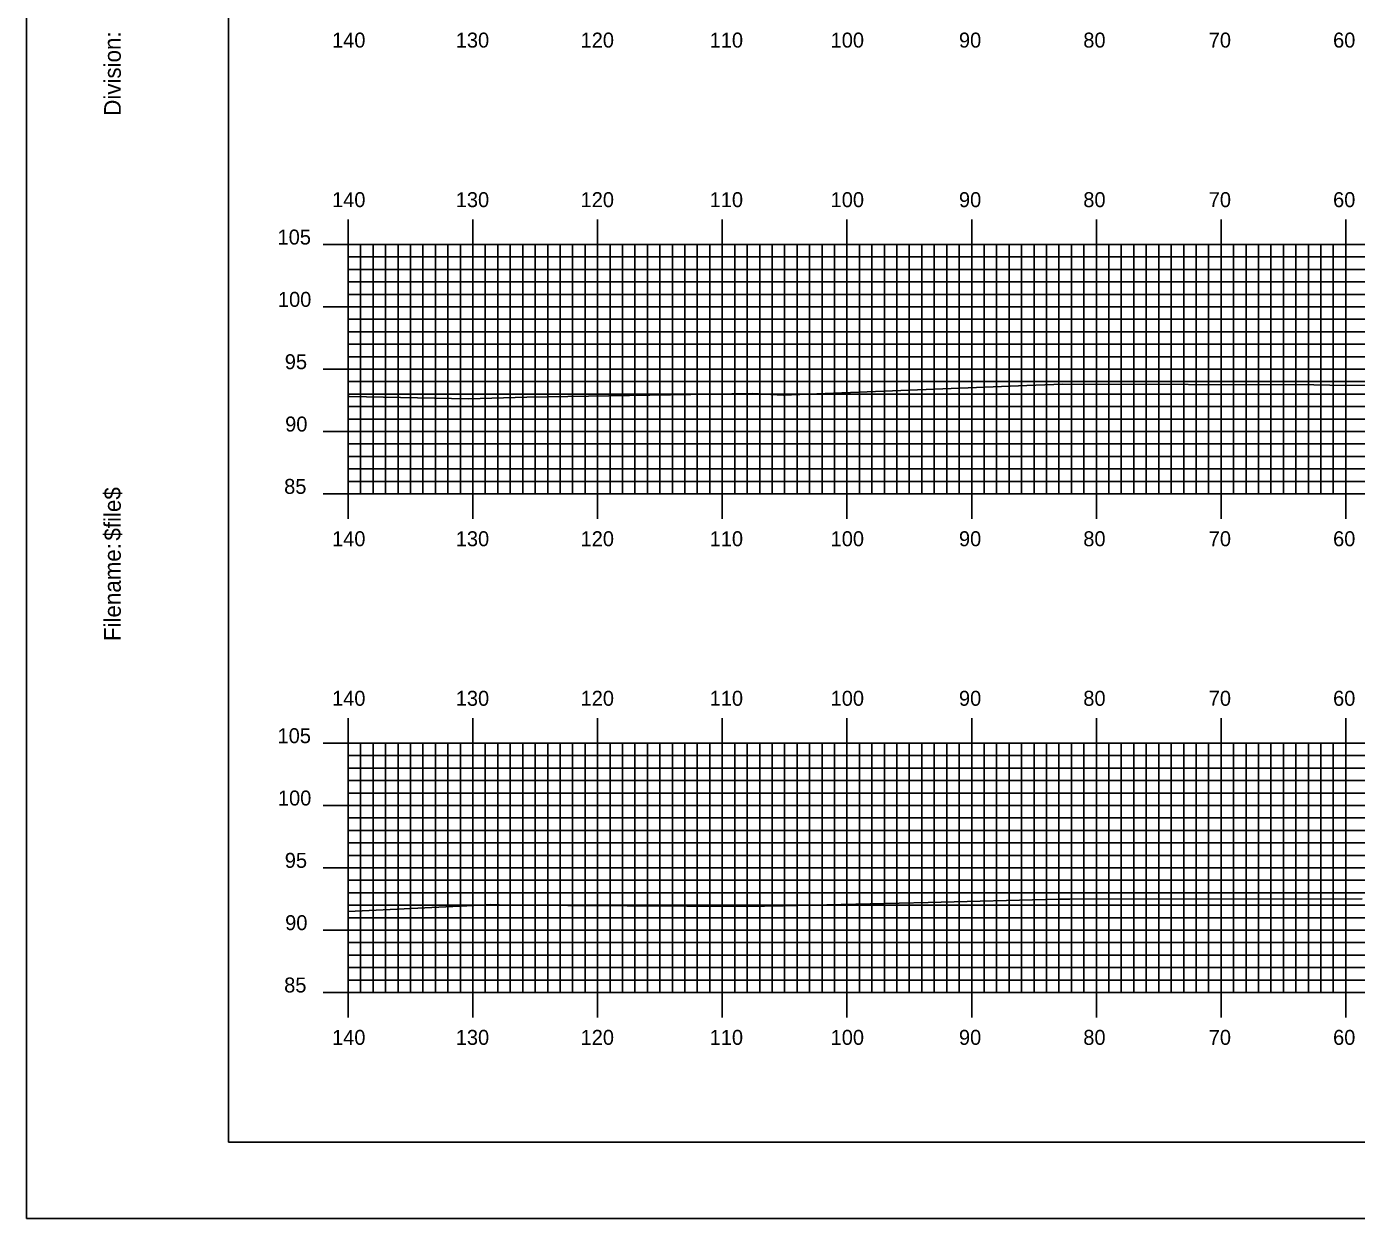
# Model space of a CAD drawing. Extents: x 1778319 to 1778662, y 442591 to 442811.
# Drawn here: x 1778318.5 to 1778425.2, y 442590.5 to 442686.2 of the extents above; entities that cross this region are included whole.
import ezdxf

# ---------------------------------------------------------------- set-up
doc = ezdxf.new("R2010")
doc.units = 0
for name, color, linetype in [('BORDER', 7, 'Continuous'), ('H_V ANNOTATION', 7, 'Continuous'), ('MAJOR', 7, 'Continuous'), ('MINOR', 7, 'Continuous'), ('PLOT BOUNDARY', 7, 'Continuous'), ('S_Roadway_Centerline', 7, 'Continuous')]:
    doc.layers.add(name, color=color, linetype=linetype)

msp = doc.modelspace()

# ---------------------------------------------------------------- linework, layer by layer
at = {"layer": 'BORDER'}
msp.add_lwpolyline([(1778334.7, 442596.67), (1778654.7, 442596.67), (1778654.7, 442806.67), (1778334.7, 442806.67)], close=True, dxfattribs=at)
at = {"layer": 'MAJOR'}
for p, q in [((1778344.3, 442670.67), (1778344.3, 442668.67)), ((1778354.3, 442670.67), (1778354.3, 442668.67)), ((1778364.3, 442670.67), (1778364.3, 442668.67)), ((1778374.3, 442670.67), (1778374.3, 442668.67)), ((1778384.3, 442670.67), (1778384.3, 442668.67)), ((1778394.3, 442670.67), (1778394.3, 442668.67)), ((1778404.3, 442670.67), (1778404.3, 442668.67)), ((1778414.3, 442670.67), (1778414.3, 442668.67)), ((1778424.3, 442670.67), (1778424.3, 442668.67)), ((1778342.3, 442668.67), (1778344.3, 442668.67)), ((1778344.3, 442668.67), (1778624.3, 442668.67)), ((1778344.3, 442648.67), (1778344.3, 442668.67)), ((1778344.3, 442648.67), (1778344.3, 442668.67)), ((1778344.3, 442668.67), (1778624.3, 442668.67)), ((1778354.3, 442648.67), (1778354.3, 442668.67)), ((1778364.3, 442648.67), (1778364.3, 442668.67)), ((1778374.3, 442648.67), (1778374.3, 442668.67)), ((1778384.3, 442648.67), (1778384.3, 442668.67)), ((1778394.3, 442648.67), (1778394.3, 442668.67)), ((1778404.3, 442648.67), (1778404.3, 442668.67)), ((1778414.3, 442648.67), (1778414.3, 442668.67)), ((1778424.3, 442648.67), (1778424.3, 442668.67)), ((1778342.3, 442663.67), (1778344.3, 442663.67)), ((1778344.3, 442663.67), (1778624.3, 442663.67)), ((1778342.3, 442658.67), (1778344.3, 442658.67)), ((1778344.3, 442658.67), (1778624.3, 442658.67)), ((1778342.3, 442653.67), (1778344.3, 442653.67)), ((1778344.3, 442653.67), (1778624.3, 442653.67)), ((1778342.3, 442648.67), (1778344.3, 442648.67)), ((1778344.3, 442648.67), (1778624.3, 442648.67)), ((1778344.3, 442648.67), (1778624.3, 442648.67)), ((1778344.3, 442646.66), (1778344.3, 442648.67)), ((1778354.3, 442646.66), (1778354.3, 442648.67)), ((1778364.3, 442646.66), (1778364.3, 442648.67)), ((1778374.3, 442646.66), (1778374.3, 442648.67)), ((1778384.3, 442646.66), (1778384.3, 442648.67)), ((1778394.3, 442646.66), (1778394.3, 442648.67)), ((1778404.3, 442646.66), (1778404.3, 442648.67)), ((1778414.3, 442646.66), (1778414.3, 442648.67)), ((1778424.3, 442646.66), (1778424.3, 442648.67)), ((1778344.3, 442630.67), (1778344.3, 442628.67)), ((1778354.3, 442630.67), (1778354.3, 442628.67)), ((1778364.3, 442630.67), (1778364.3, 442628.67)), ((1778374.3, 442630.67), (1778374.3, 442628.67)), ((1778384.3, 442630.67), (1778384.3, 442628.67)), ((1778394.3, 442630.67), (1778394.3, 442628.67)), ((1778404.3, 442630.67), (1778404.3, 442628.67)), ((1778414.3, 442630.67), (1778414.3, 442628.67)), ((1778424.3, 442630.67), (1778424.3, 442628.67)), ((1778342.3, 442628.67), (1778344.3, 442628.67)), ((1778344.3, 442628.67), (1778624.3, 442628.67)), ((1778344.3, 442608.67), (1778344.3, 442628.67)), ((1778344.3, 442608.67), (1778344.3, 442628.67)), ((1778344.3, 442628.67), (1778624.3, 442628.67)), ((1778354.3, 442608.67), (1778354.3, 442628.67)), ((1778364.3, 442608.67), (1778364.3, 442628.67)), ((1778374.3, 442608.67), (1778374.3, 442628.67)), ((1778384.3, 442608.67), (1778384.3, 442628.67)), ((1778394.3, 442608.67), (1778394.3, 442628.67)), ((1778404.3, 442608.67), (1778404.3, 442628.67)), ((1778414.3, 442608.67), (1778414.3, 442628.67)), ((1778424.3, 442608.67), (1778424.3, 442628.67)), ((1778342.3, 442623.67), (1778344.3, 442623.67)), ((1778344.3, 442623.67), (1778624.3, 442623.67)), ((1778342.3, 442618.67), (1778344.3, 442618.67)), ((1778344.3, 442618.67), (1778624.3, 442618.67)), ((1778342.3, 442613.67), (1778344.3, 442613.67)), ((1778344.3, 442613.67), (1778624.3, 442613.67)), ((1778342.3, 442608.67), (1778344.3, 442608.67)), ((1778344.3, 442608.67), (1778624.3, 442608.67)), ((1778344.3, 442608.67), (1778624.3, 442608.67)), ((1778344.3, 442606.66), (1778344.3, 442608.67)), ((1778354.3, 442606.66), (1778354.3, 442608.67)), ((1778364.3, 442606.66), (1778364.3, 442608.67)), ((1778374.3, 442606.66), (1778374.3, 442608.67)), ((1778384.3, 442606.66), (1778384.3, 442608.67)), ((1778394.3, 442606.66), (1778394.3, 442608.67)), ((1778404.3, 442606.66), (1778404.3, 442608.67)), ((1778414.3, 442606.66), (1778414.3, 442608.67)), ((1778424.3, 442606.66), (1778424.3, 442608.67))]:
    msp.add_line(p, q, dxfattribs=at)
at = {"layer": 'MINOR'}
for p, q in [((1778345.3, 442648.67), (1778345.3, 442668.67)), ((1778346.3, 442648.67), (1778346.3, 442668.67)), ((1778347.3, 442648.67), (1778347.3, 442668.67)), ((1778348.3, 442648.67), (1778348.3, 442668.67)), ((1778349.3, 442648.67), (1778349.3, 442668.67)), ((1778350.3, 442648.67), (1778350.3, 442668.67)), ((1778351.3, 442648.67), (1778351.3, 442668.67)), ((1778352.3, 442648.67), (1778352.3, 442668.67)), ((1778353.3, 442648.67), (1778353.3, 442668.67)), ((1778355.3, 442648.67), (1778355.3, 442668.67)), ((1778356.3, 442648.67), (1778356.3, 442668.67)), ((1778357.3, 442648.67), (1778357.3, 442668.67)), ((1778358.3, 442648.67), (1778358.3, 442668.67)), ((1778359.3, 442648.67), (1778359.3, 442668.67)), ((1778360.3, 442648.67), (1778360.3, 442668.67)), ((1778361.3, 442648.67), (1778361.3, 442668.67)), ((1778362.3, 442648.67), (1778362.3, 442668.67)), ((1778363.3, 442648.67), (1778363.3, 442668.67)), ((1778365.3, 442648.67), (1778365.3, 442668.67)), ((1778366.3, 442648.67), (1778366.3, 442668.67)), ((1778367.3, 442648.67), (1778367.3, 442668.67)), ((1778368.3, 442648.67), (1778368.3, 442668.67)), ((1778369.3, 442648.67), (1778369.3, 442668.67)), ((1778370.3, 442648.67), (1778370.3, 442668.67)), ((1778371.3, 442648.67), (1778371.3, 442668.67)), ((1778372.3, 442648.67), (1778372.3, 442668.67)), ((1778373.3, 442648.67), (1778373.3, 442668.67)), ((1778375.3, 442648.67), (1778375.3, 442668.67)), ((1778376.3, 442648.67), (1778376.3, 442668.67)), ((1778377.3, 442648.67), (1778377.3, 442668.67)), ((1778378.3, 442648.67), (1778378.3, 442668.67)), ((1778379.3, 442648.67), (1778379.3, 442668.67)), ((1778380.3, 442648.67), (1778380.3, 442668.67)), ((1778381.3, 442648.67), (1778381.3, 442668.67)), ((1778382.3, 442648.67), (1778382.3, 442668.67)), ((1778383.3, 442648.67), (1778383.3, 442668.67)), ((1778385.3, 442648.67), (1778385.3, 442668.67)), ((1778386.3, 442648.67), (1778386.3, 442668.67)), ((1778387.3, 442648.67), (1778387.3, 442668.67)), ((1778388.3, 442648.67), (1778388.3, 442668.67)), ((1778389.3, 442648.67), (1778389.3, 442668.67)), ((1778390.3, 442648.67), (1778390.3, 442668.67)), ((1778391.3, 442648.67), (1778391.3, 442668.67)), ((1778392.3, 442648.67), (1778392.3, 442668.67)), ((1778393.3, 442648.67), (1778393.3, 442668.67)), ((1778395.3, 442648.67), (1778395.3, 442668.67)), ((1778396.3, 442648.67), (1778396.3, 442668.67)), ((1778397.3, 442648.67), (1778397.3, 442668.67)), ((1778398.3, 442648.67), (1778398.3, 442668.67)), ((1778399.3, 442648.67), (1778399.3, 442668.67)), ((1778400.3, 442648.67), (1778400.3, 442668.67)), ((1778401.3, 442648.67), (1778401.3, 442668.67)), ((1778402.3, 442648.67), (1778402.3, 442668.67)), ((1778403.3, 442648.67), (1778403.3, 442668.67)), ((1778405.3, 442648.67), (1778405.3, 442668.67)), ((1778406.3, 442648.67), (1778406.3, 442668.67)), ((1778407.3, 442648.67), (1778407.3, 442668.67)), ((1778408.3, 442648.67), (1778408.3, 442668.67)), ((1778409.3, 442648.67), (1778409.3, 442668.67)), ((1778410.3, 442648.67), (1778410.3, 442668.67)), ((1778411.3, 442648.67), (1778411.3, 442668.67)), ((1778412.3, 442648.67), (1778412.3, 442668.67)), ((1778413.3, 442648.67), (1778413.3, 442668.67)), ((1778415.3, 442648.67), (1778415.3, 442668.67)), ((1778416.3, 442648.67), (1778416.3, 442668.67)), ((1778417.3, 442648.67), (1778417.3, 442668.67)), ((1778418.3, 442648.67), (1778418.3, 442668.67)), ((1778419.3, 442648.67), (1778419.3, 442668.67)), ((1778420.3, 442648.67), (1778420.3, 442668.67)), ((1778421.3, 442648.67), (1778421.3, 442668.67)), ((1778422.3, 442648.67), (1778422.3, 442668.67)), ((1778423.3, 442648.67), (1778423.3, 442668.67)), ((1778344.3, 442667.67), (1778624.3, 442667.67)), ((1778344.3, 442667.67), (1778346.31, 442667.67)), ((1778344.3, 442666.67), (1778624.3, 442666.67)), ((1778344.3, 442666.67), (1778346.31, 442666.67)), ((1778344.3, 442665.67), (1778624.3, 442665.67)), ((1778344.3, 442665.67), (1778346.31, 442665.67)), ((1778344.3, 442664.67), (1778624.3, 442664.67)), ((1778344.3, 442664.67), (1778346.31, 442664.67)), ((1778344.3, 442662.67), (1778624.3, 442662.67)), ((1778344.3, 442662.67), (1778346.31, 442662.67)), ((1778344.3, 442661.67), (1778624.3, 442661.67)), ((1778344.3, 442661.67), (1778346.31, 442661.67)), ((1778344.3, 442660.67), (1778624.3, 442660.67)), ((1778344.3, 442660.67), (1778346.31, 442660.67)), ((1778344.3, 442659.67), (1778624.3, 442659.67)), ((1778344.3, 442659.67), (1778346.31, 442659.67)), ((1778344.3, 442657.67), (1778624.3, 442657.67)), ((1778344.3, 442657.67), (1778346.31, 442657.67)), ((1778344.3, 442656.67), (1778624.3, 442656.67)), ((1778344.3, 442656.67), (1778346.31, 442656.67)), ((1778344.3, 442655.67), (1778624.3, 442655.67)), ((1778344.3, 442655.67), (1778346.31, 442655.67)), ((1778344.3, 442654.67), (1778624.3, 442654.67)), ((1778344.3, 442654.67), (1778346.31, 442654.67)), ((1778344.3, 442652.67), (1778624.3, 442652.67)), ((1778344.3, 442652.67), (1778346.31, 442652.67)), ((1778344.3, 442651.67), (1778624.3, 442651.67)), ((1778344.3, 442651.67), (1778346.31, 442651.67)), ((1778344.3, 442650.67), (1778624.3, 442650.67)), ((1778344.3, 442650.67), (1778346.31, 442650.67)), ((1778344.3, 442649.67), (1778624.3, 442649.67)), ((1778344.3, 442649.67), (1778346.31, 442649.67)), ((1778345.3, 442608.67), (1778345.3, 442628.67)), ((1778346.3, 442608.67), (1778346.3, 442628.67)), ((1778347.3, 442608.67), (1778347.3, 442628.67)), ((1778348.3, 442608.67), (1778348.3, 442628.67)), ((1778349.3, 442608.67), (1778349.3, 442628.67)), ((1778350.3, 442608.67), (1778350.3, 442628.67)), ((1778351.3, 442608.67), (1778351.3, 442628.67)), ((1778352.3, 442608.67), (1778352.3, 442628.67)), ((1778353.3, 442608.67), (1778353.3, 442628.67)), ((1778355.3, 442608.67), (1778355.3, 442628.67)), ((1778356.3, 442608.67), (1778356.3, 442628.67)), ((1778357.3, 442608.67), (1778357.3, 442628.67)), ((1778358.3, 442608.67), (1778358.3, 442628.67)), ((1778359.3, 442608.67), (1778359.3, 442628.67)), ((1778360.3, 442608.67), (1778360.3, 442628.67)), ((1778361.3, 442608.67), (1778361.3, 442628.67)), ((1778362.3, 442608.67), (1778362.3, 442628.67)), ((1778363.3, 442608.67), (1778363.3, 442628.67)), ((1778365.3, 442608.67), (1778365.3, 442628.67)), ((1778366.3, 442608.67), (1778366.3, 442628.67)), ((1778367.3, 442608.67), (1778367.3, 442628.67)), ((1778368.3, 442608.67), (1778368.3, 442628.67)), ((1778369.3, 442608.67), (1778369.3, 442628.67)), ((1778370.3, 442608.67), (1778370.3, 442628.67)), ((1778371.3, 442608.67), (1778371.3, 442628.67)), ((1778372.3, 442608.67), (1778372.3, 442628.67)), ((1778373.3, 442608.67), (1778373.3, 442628.67)), ((1778375.3, 442608.67), (1778375.3, 442628.67)), ((1778376.3, 442608.67), (1778376.3, 442628.67)), ((1778377.3, 442608.67), (1778377.3, 442628.67)), ((1778378.3, 442608.67), (1778378.3, 442628.67)), ((1778379.3, 442608.67), (1778379.3, 442628.67)), ((1778380.3, 442608.67), (1778380.3, 442628.67)), ((1778381.3, 442608.67), (1778381.3, 442628.67)), ((1778382.3, 442608.67), (1778382.3, 442628.67)), ((1778383.3, 442608.67), (1778383.3, 442628.67)), ((1778385.3, 442608.67), (1778385.3, 442628.67)), ((1778386.3, 442608.67), (1778386.3, 442628.67)), ((1778387.3, 442608.67), (1778387.3, 442628.67)), ((1778388.3, 442608.67), (1778388.3, 442628.67)), ((1778389.3, 442608.67), (1778389.3, 442628.67)), ((1778390.3, 442608.67), (1778390.3, 442628.67)), ((1778391.3, 442608.67), (1778391.3, 442628.67)), ((1778392.3, 442608.67), (1778392.3, 442628.67)), ((1778393.3, 442608.67), (1778393.3, 442628.67)), ((1778395.3, 442608.67), (1778395.3, 442628.67)), ((1778396.3, 442608.67), (1778396.3, 442628.67)), ((1778397.3, 442608.67), (1778397.3, 442628.67)), ((1778398.3, 442608.67), (1778398.3, 442628.67)), ((1778399.3, 442608.67), (1778399.3, 442628.67)), ((1778400.3, 442608.67), (1778400.3, 442628.67)), ((1778401.3, 442608.67), (1778401.3, 442628.67)), ((1778402.3, 442608.67), (1778402.3, 442628.67)), ((1778403.3, 442608.67), (1778403.3, 442628.67)), ((1778405.3, 442608.67), (1778405.3, 442628.67)), ((1778406.3, 442608.67), (1778406.3, 442628.67)), ((1778407.3, 442608.67), (1778407.3, 442628.67)), ((1778408.3, 442608.67), (1778408.3, 442628.67)), ((1778409.3, 442608.67), (1778409.3, 442628.67)), ((1778410.3, 442608.67), (1778410.3, 442628.67)), ((1778411.3, 442608.67), (1778411.3, 442628.67)), ((1778412.3, 442608.67), (1778412.3, 442628.67)), ((1778413.3, 442608.67), (1778413.3, 442628.67)), ((1778415.3, 442608.67), (1778415.3, 442628.67)), ((1778416.3, 442608.67), (1778416.3, 442628.67)), ((1778417.3, 442608.67), (1778417.3, 442628.67)), ((1778418.3, 442608.67), (1778418.3, 442628.67)), ((1778419.3, 442608.67), (1778419.3, 442628.67)), ((1778420.3, 442608.67), (1778420.3, 442628.67)), ((1778421.3, 442608.67), (1778421.3, 442628.67)), ((1778422.3, 442608.67), (1778422.3, 442628.67)), ((1778423.3, 442608.67), (1778423.3, 442628.67)), ((1778344.3, 442627.67), (1778624.3, 442627.67)), ((1778344.3, 442627.67), (1778346.31, 442627.67)), ((1778344.3, 442626.67), (1778624.3, 442626.67)), ((1778344.3, 442626.67), (1778346.31, 442626.67)), ((1778344.3, 442625.67), (1778624.3, 442625.67)), ((1778344.3, 442625.67), (1778346.31, 442625.67)), ((1778344.3, 442624.67), (1778624.3, 442624.67)), ((1778344.3, 442624.67), (1778346.31, 442624.67)), ((1778344.3, 442622.67), (1778624.3, 442622.67)), ((1778344.3, 442622.67), (1778346.31, 442622.67)), ((1778344.3, 442621.67), (1778624.3, 442621.67)), ((1778344.3, 442621.67), (1778346.31, 442621.67)), ((1778344.3, 442620.67), (1778624.3, 442620.67)), ((1778344.3, 442620.67), (1778346.31, 442620.67)), ((1778344.3, 442619.67), (1778624.3, 442619.67)), ((1778344.3, 442619.67), (1778346.31, 442619.67)), ((1778344.3, 442617.67), (1778624.3, 442617.67)), ((1778344.3, 442617.67), (1778346.31, 442617.67)), ((1778344.3, 442616.67), (1778624.3, 442616.67)), ((1778344.3, 442616.67), (1778346.31, 442616.67)), ((1778344.3, 442615.67), (1778624.3, 442615.67)), ((1778344.3, 442615.67), (1778346.31, 442615.67)), ((1778344.3, 442614.67), (1778624.3, 442614.67)), ((1778344.3, 442614.67), (1778346.31, 442614.67)), ((1778344.3, 442612.67), (1778624.3, 442612.67)), ((1778344.3, 442612.67), (1778346.31, 442612.67)), ((1778344.3, 442611.67), (1778624.3, 442611.67)), ((1778344.3, 442611.67), (1778346.31, 442611.67)), ((1778344.3, 442610.67), (1778624.3, 442610.67)), ((1778344.3, 442610.67), (1778346.31, 442610.67)), ((1778344.3, 442609.67), (1778624.3, 442609.67)), ((1778344.3, 442609.67), (1778346.31, 442609.67))]:
    msp.add_line(p, q, dxfattribs=at)
at = {"layer": 'PLOT BOUNDARY'}
msp.add_lwpolyline([(1778318.52, 442590.55), (1778658.52, 442590.55), (1778658.52, 442810.55), (1778318.52, 442810.55)], close=True, dxfattribs=at)
at = {"layer": 'S_Roadway_Centerline'}
for points in [[(1778344.3, 442656.47), (1778344.4, 442656.48), (1778353.96, 442656.28), (1778358.63, 442656.43), (1778376.72, 442656.73), (1778379.18, 442656.58), (1778398.72, 442657.35), (1778401.62, 442657.47), (1778421.74, 442657.42), (1778424.3, 442657.37), (1778429.2, 442657.4), (1778437.29, 442657.57), (1778444.88, 442657.44), (1778449.46, 442657.46), (1778453.95, 442657.36), (1778467.41, 442657.47), (1778477.36, 442657.68), (1778490.65, 442658.22), (1778501.32, 442658.22), (1778507.27, 442657.93), (1778512.45, 442657.91), (1778518.54, 442657.93), (1778524.41, 442658.02), (1778539.78, 442658.08)], [(1778344.3, 442615.16), (1778354.37, 442615.64), (1778355.72, 442615.72), (1778357.14, 442615.68), (1778376.23, 442615.58), (1778379.19, 442615.63), (1778390.82, 442615.9), (1778401.27, 442616.15), (1778401.7, 442616.15), (1778402.18, 442616.15), (1778425.62, 442616.17)]]:
    msp.add_lwpolyline(points, dxfattribs=at)

# ---------------------------------------------------------------- texts
at = {"layer": 'BORDER'}
for s, p in [('Division:', (1778326.07, 442679)), ('$file$', (1778326.07, 442644.92)), ('Filename:', (1778326.07, 442636.86))]:
    msp.add_text(s, height=1.339, rotation=90, dxfattribs=at).set_placement(p)
at = {"layer": 'H_V ANNOTATION'}
for s, p in [('140', (1778343.01, 442684.47)), ('130', (1778352.93, 442684.47)), ('120', (1778362.94, 442684.47)), ('110', (1778373.29, 442684.47)), ('100', (1778382.99, 442684.47)), ('90', (1778393.28, 442684.47)), ('80', (1778403.25, 442684.47)), ('70', (1778413.31, 442684.47)), ('60', (1778423.28, 442684.47)), ('140', (1778343.01, 442671.67)), ('130', (1778352.93, 442671.67)), ('120', (1778362.94, 442671.67)), ('110', (1778373.29, 442671.67)), ('100', (1778382.99, 442671.67)), ('90', (1778393.28, 442671.67)), ('80', (1778403.25, 442671.67)), ('70', (1778413.31, 442671.67)), ('60', (1778423.28, 442671.67)), ('105', (1778338.64, 442668.67)), ('100', (1778338.67, 442663.67)), ('95', (1778339.22, 442658.67)), ('90', (1778339.25, 442653.67)), ('85', (1778339.17, 442648.67)), ('140', (1778343.01, 442644.47)), ('130', (1778352.93, 442644.47)), ('120', (1778362.94, 442644.47)), ('110', (1778373.29, 442644.47)), ('100', (1778382.99, 442644.47)), ('90', (1778393.28, 442644.47)), ('80', (1778403.25, 442644.47)), ('70', (1778413.31, 442644.47)), ('60', (1778423.28, 442644.47)), ('140', (1778343.01, 442631.67)), ('130', (1778352.93, 442631.67)), ('120', (1778362.94, 442631.67)), ('110', (1778373.29, 442631.67)), ('100', (1778382.99, 442631.67)), ('90', (1778393.28, 442631.67)), ('80', (1778403.25, 442631.67)), ('70', (1778413.31, 442631.67)), ('60', (1778423.28, 442631.67)), ('105', (1778338.64, 442628.67)), ('100', (1778338.67, 442623.67)), ('95', (1778339.22, 442618.67)), ('90', (1778339.25, 442613.67)), ('85', (1778339.17, 442608.67)), ('140', (1778343.01, 442604.47)), ('130', (1778352.93, 442604.47)), ('120', (1778362.94, 442604.47)), ('110', (1778373.29, 442604.47)), ('100', (1778382.99, 442604.47)), ('90', (1778393.28, 442604.47)), ('80', (1778403.25, 442604.47)), ('70', (1778413.31, 442604.47)), ('60', (1778423.28, 442604.47))]:
    msp.add_text(s, height=1.2, dxfattribs=at).set_placement(p)
at = {"layer": 'MAJOR'}
for p in [(1778344.29, 442648.67), (1778344.29, 442608.67)]:
    msp.add_text('-', height=0.012, dxfattribs=at).set_placement(p)

doc.saveas('drawing.dxf')
